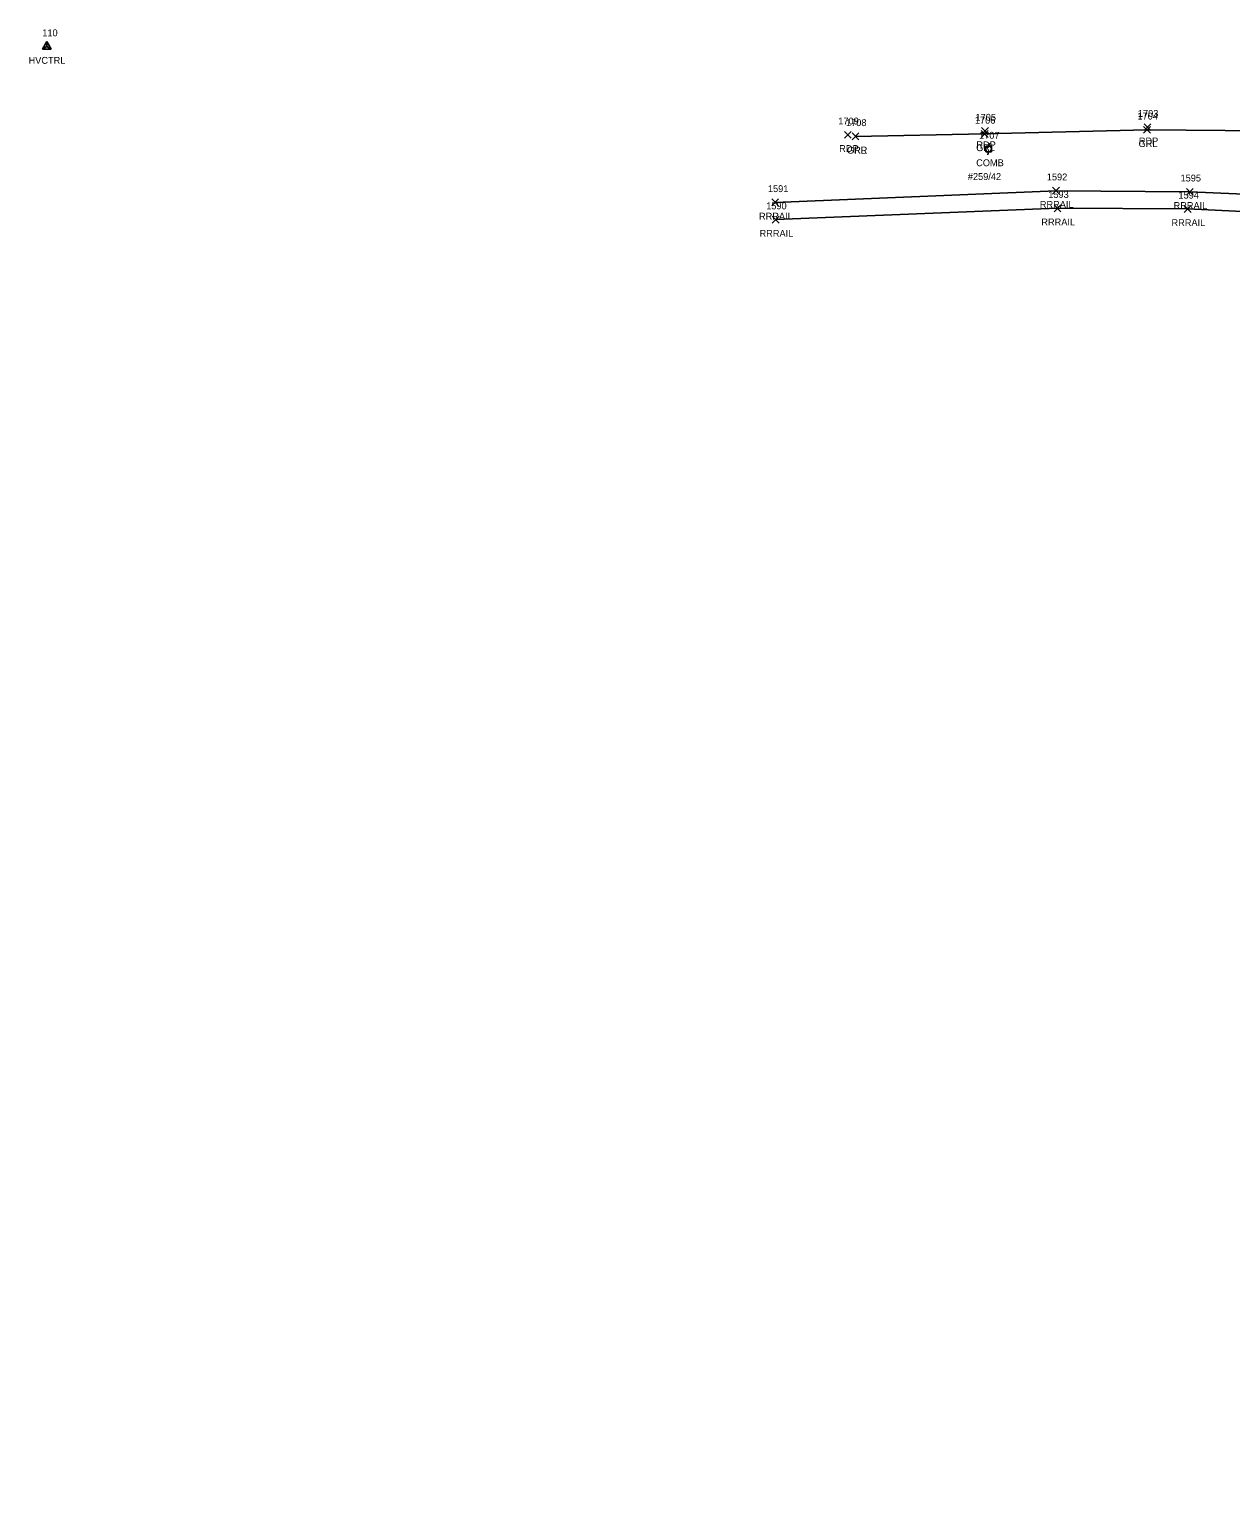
# Model space of a CAD drawing. Extents: x 1635588 to 1637550, y 621583 to 623638.
# Drawn here: x 1635587.6 to 1635936.7, y 623212.1 to 623638.1 of the extents above; entities that cross this region are included whole.
import ezdxf

# ---------------------------------------------------------------- set-up
doc = ezdxf.new("R2010")
doc.units = 0
for name, color, linetype in [('C_A', 7, 'Continuous'), ('C_I', 7, 'Continuous'), ('CPSM', 7, 'Continuous'), ('P_A', 7, 'Continuous'), ('P_I', 7, 'Continuous'), ('P_TIC', 7, 'Continuous'), ('R_A', 7, 'Continuous'), ('R_I', 7, 'Continuous'), ('R_TIC', 7, 'Continuous'), ('RGR', 7, 'Continuous'), ('RR', 7, 'Continuous'), ('U_A', 7, 'Continuous'), ('U_C', 7, 'Continuous'), ('U_I', 7, 'Continuous'), ('UP', 7, 'Continuous')]:
    doc.layers.add(name, color=color, linetype=linetype)

msp = doc.modelspace()

# ---------------------------------------------------------------- linework, layer by layer
at = {"layer": 'CPSM'}
for p, q in [((1635591.45, 623632.35), (1635592.7, 623634.52)), ((1635591.45, 623632.35), (1635592.7, 623633.08)), ((1635591.45, 623632.35), (1635593.95, 623632.35)), ((1635593.95, 623632.35), (1635592.7, 623634.52)), ((1635592.7, 623633.08), (1635592.7, 623634.52)), ((1635592.7, 623633.08), (1635592.7, 623633.08)), ((1635592.7, 623633.08), (1635593.95, 623632.35))]:
    msp.add_line(p, q, dxfattribs=at)
at = {"layer": 'P_TIC'}
for points in [[(1635864.35, 623607.53), (1635866.35, 623609.53)], [(1635866.35, 623607.53), (1635864.35, 623609.53)], [(1635911.56, 623608.65), (1635913.56, 623610.65)], [(1635913.56, 623608.65), (1635911.56, 623610.65)], [(1635824.48, 623606.44), (1635826.48, 623608.44)], [(1635826.48, 623606.44), (1635824.48, 623608.44)], [(1635824.48, 623606.44), (1635826.48, 623608.44)], [(1635826.48, 623606.44), (1635824.48, 623608.44)]]:
    msp.add_lwpolyline(points, dxfattribs=at)
at = {"layer": 'R_TIC'}
for points in [[(1635911.43, 623607.87), (1635913.43, 623609.87)], [(1635913.43, 623607.87), (1635911.43, 623609.87)], [(1635826.72, 623605.97), (1635828.72, 623607.97)], [(1635828.72, 623605.97), (1635826.72, 623607.97)], [(1635826.72, 623605.97), (1635828.72, 623607.97)], [(1635828.72, 623605.97), (1635826.72, 623607.97)], [(1635864.23, 623606.69), (1635866.23, 623608.69)], [(1635866.23, 623606.69), (1635864.23, 623608.69)], [(1635803.38, 623586.78), (1635805.38, 623588.78)], [(1635805.38, 623586.78), (1635803.38, 623588.78)], [(1635885, 623590.18), (1635887, 623592.18)], [(1635887, 623590.18), (1635885, 623592.18)], [(1635923.86, 623589.87), (1635925.86, 623591.87)], [(1635925.86, 623589.87), (1635923.86, 623591.87)], [(1635885.42, 623585.09), (1635887.42, 623587.09)], [(1635887.42, 623585.09), (1635885.42, 623587.09)], [(1635923.26, 623584.89), (1635925.26, 623586.89)], [(1635925.26, 623584.89), (1635923.26, 623586.89)], [(1635803.54, 623581.78), (1635805.54, 623583.78)], [(1635805.54, 623581.78), (1635803.54, 623583.78)]]:
    msp.add_lwpolyline(points, dxfattribs=at)
at = {"layer": 'RGR'}
msp.add_lwpolyline([(1636305.19, 623409.8), (1636285.27, 623437.15), (1636262.93, 623463.31), (1636244.49, 623481.3), (1636221.25, 623502.22), (1636196.64, 623521.56), (1636184.56, 623529.81), (1636170.14, 623538.98), (1636148.75, 623550.67), (1636126.46, 623562.53), (1636102.16, 623574.13), (1636080.92, 623582.58), (1636057.23, 623590.14), (1636051.08, 623591.93), (1636027.07, 623598.42), (1636002.44, 623603.08), (1635977.33, 623606.41), (1635946.46, 623608.63), (1635912.43, 623608.87), (1635865.23, 623607.69), (1635827.72, 623606.97)], dxfattribs=at)
at = {"layer": 'RR'}
for points in [[(1635804.38, 623587.78), (1635886, 623591.18), (1635924.86, 623590.87), (1635951.97, 623589.69), (1635990.42, 623585.12), (1636025.5, 623577.68), (1636061.16, 623567.3), (1636080.11, 623560.16), (1636116.76, 623544.58), (1636140.64, 623532.31), (1636172.21, 623513.66), (1636196.85, 623496.79), (1636223, 623476.01), (1636248.62, 623451.82), (1636277.3, 623421.48), (1636310.55, 623379.63), (1636333.74, 623345.07), (1636353.23, 623312.06), (1636372.67, 623275.5), (1636403.41, 623214.43)], [(1635804.54, 623582.78), (1635886.42, 623586.09), (1635924.26, 623585.89), (1635952.04, 623584.59), (1635989.32, 623580.18), (1636024.35, 623572.88), (1636059.67, 623562.36), (1636078.46, 623555.55), (1636114.37, 623540.19), (1636138.58, 623527.78), (1636169.41, 623509.57), (1636193.73, 623492.88), (1636219.9, 623472.06), (1636245.31, 623448.34), (1636273.58, 623418.05), (1636306.45, 623376.76), (1636329.74, 623342.31), (1636348.93, 623309.65), (1636368.15, 623273.24), (1636399.35, 623212.11)]]:
    msp.add_lwpolyline(points, dxfattribs=at)
at = {"layer": 'UP'}
for p, q in [((1635865.56, 623602.47), (1635865.56, 623604.14)), ((1635865.56, 623604.14), (1635867.23, 623604.14)), ((1635867.23, 623602.47), (1635865.56, 623602.47)), ((1635866.14, 623601.64), (1635866.39, 623602.47)), ((1635866.64, 623604.97), (1635866.39, 623604.14)), ((1635866.39, 623603.3), (1635866.39, 623603.3)), ((1635867.23, 623604.14), (1635867.23, 623602.47))]:
    msp.add_line(p, q, dxfattribs=at)
msp.add_circle((1635866.39, 623603.3), 0.833, dxfattribs=at)

# ---------------------------------------------------------------- texts
at = {"layer": 'C_A'}
msp.add_text('HVCTRL', height=2, dxfattribs=at).set_placement((1635587.39, 623628.08))
at = {"layer": 'C_I'}
msp.add_text('110', height=2, dxfattribs=at).set_placement((1635591.38, 623636.08))
at = {"layer": 'P_A'}
for p in [(1635862.84, 623603.53), (1635910.04, 623604.65), (1635822.97, 623602.44), (1635822.97, 623602.44)]:
    msp.add_text('RDP', height=2, dxfattribs=at).set_placement(p)
at = {"layer": 'P_I'}
for s, p in [('1703', (1635909.78, 623612.65)), ('1709', (1635822.7, 623610.44)), ('1709', (1635822.7, 623610.44)), ('1705', (1635862.58, 623611.53))]:
    msp.add_text(s, height=2, dxfattribs=at).set_placement(p)
at = {"layer": 'R_A'}
for s, p in [('GRL', (1635909.98, 623603.87)), ('GRR', (1635825.21, 623601.97)), ('GRL', (1635825.26, 623601.97)), ('GRL', (1635862.77, 623602.69)), ('RRRAIL', (1635881.29, 623586.18)), ('RRRAIL', (1635799.67, 623582.78)), ('RRRAIL', (1635920.15, 623585.87)), ('RRRAIL', (1635799.83, 623577.78)), ('RRRAIL', (1635881.72, 623581.09)), ('RRRAIL', (1635919.55, 623580.89))]:
    msp.add_text(s, height=2, dxfattribs=at).set_placement(p)
at = {"layer": 'R_I'}
for s, p in [('1704', (1635909.66, 623611.87)), ('1708', (1635824.95, 623609.97)), ('1708', (1635824.95, 623609.97)), ('1706', (1635862.41, 623610.69)), ('1591', (1635802.26, 623590.78)), ('1592', (1635883.31, 623594.18)), ('1595', (1635922.17, 623593.87)), ('1593', (1635883.73, 623589.09)), ('1594', (1635921.57, 623588.89)), ('1590', (1635801.76, 623585.78))]:
    msp.add_text(s, height=2, dxfattribs=at).set_placement(p)
at = {"layer": 'U_A'}
msp.add_text('COMB', height=2, dxfattribs=at).set_placement((1635862.78, 623598.3))
at = {"layer": 'U_C'}
msp.add_text('#259/42', height=2, dxfattribs=at).set_placement((1635860.36, 623594.3))
at = {"layer": 'U_I'}
msp.add_text('1707', height=2, dxfattribs=at).set_placement((1635863.62, 623606.3))

doc.saveas('drawing.dxf')
